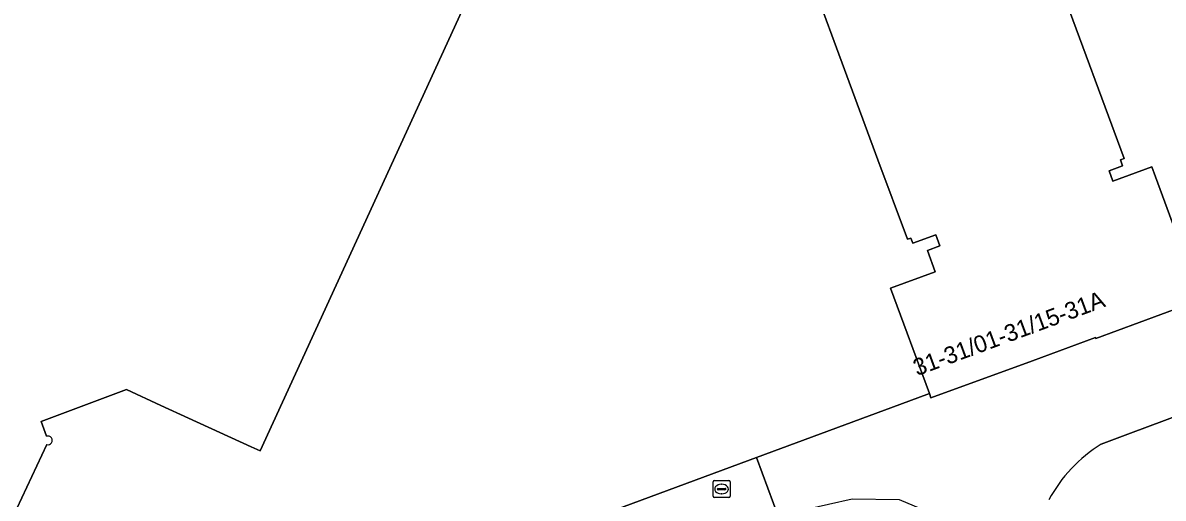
# Model space of a CAD drawing. Extents: x 160806 to 161707, y 383696 to 384148.
# Drawn here: x 160990.2 to 161057.4, y 383902 to 383930 of the extents above; entities that cross this region are included whole.
import ezdxf

# ---------------------------------------------------------------- set-up
doc = ezdxf.new("R2010")
doc.units = 0
for name, color, linetype in [('IMGEO_Pand', 7, 'Continuous'), ('IMGEO_Pand_nummerreeks', 7, 'Continuous'), ('IMGEO_Rijbaan_lokaal_gesloten', 7, 'Continuous'), ('IMGEO_Rijbaan_lokaal_open', 7, 'Continuous'), ('IMGEO_Rioolput', 7, 'Continuous'), ('IMGEO_Terreindeel_gesloten', 7, 'Continuous'), ('IMGEO_Voetpad_open', 7, 'Continuous')]:
    doc.layers.add(name, color=color, linetype=linetype)

msp = doc.modelspace()

# ---------------------------------------------------------------- linework, layer by layer
at = {"layer": 'IMGEO_Pand'}
for points in [[(161058.676, 383916.245), (161056.943, 383920.935), (161056.726, 383921.521), (161054.435, 383920.674), (161054.205, 383921.295), (161055.004, 383921.59), (161054.873, 383921.943), (161055.094, 383922.025), (161047.599, 383942.307)], [(161034.831, 383937.553), (161040.599, 383921.947), (161042.332, 383917.257), (161042.54, 383917.334), (161042.655, 383917.023), (161043.998, 383917.519), (161044.238, 383916.87), (161043.507, 383916.6), (161043.975, 383915.334), (161041.34, 383914.377), (161043.624, 383908.173), (161043.72, 383907.911), (161049.695, 383910.101), (161053.4, 383911.47), (161053.421, 383911.413), (161058.534, 383913.302)], [(160991.646, 383905.654), (160991.322, 383906.532), (160996.345, 383908.4), (160998.375, 383907.467), (161000, 383906.721), (161003.7, 383905.021), (161004.216, 383904.789), (161006.3, 383909.334), (161016.1, 383930.706)], [(160989.606, 383900.762), (160991.657, 383905.16)]]:
    msp.add_lwpolyline(points, dxfattribs=at)
msp.add_arc((160991.722, 383905.409), 0.257, 255.32376, 107.22745, dxfattribs=at)
at = {"layer": 'IMGEO_Rijbaan_lokaal_gesloten'}
for points in [[(161060.631, 383907.756), (161066.551, 383909.97), (161065.506, 383912.776), (161064.49, 383915.503), (161058.534, 383913.302), (161053.421, 383911.413), (161053.4, 383911.47), (161049.695, 383910.101), (161043.72, 383907.911), (161043.624, 383908.173), (161042.42, 383907.727), (161033.437, 383904.394), (161034.783, 383900.781), (161036.286, 383901.335), (161039.086, 383901.965), (161041.846, 383901.934), (161043.103, 383901.391), (161044.432, 383899.991), (161044.961, 383898.608), (161045.706, 383896.613), (161049.823, 383898.173)], [(161053.746, 383905.182), (161055.478, 383905.83), (161060.631, 383907.756)]]:
    msp.add_lwpolyline(points, dxfattribs=at)
msp.add_arc((161058.187, 383897.914), 8.517, 121.42514, 152.03536, dxfattribs=at)
at = {"layer": 'IMGEO_Rijbaan_lokaal_open'}
msp.add_lwpolyline([(160943.158, 383950.097), (160950.161, 383931.007), (160960.137, 383903.811), (160959.806, 383902.516), (160968.05, 383879.828), (160984.869, 383885.974), (160986.341, 383885.715), (160990.275, 383885.032), (160991.432, 383884.817), (161000, 383887.972), (161034.783, 383900.781), (161033.437, 383904.394), (161000, 383892.005), (160990.074, 383888.326), (160982.677, 383889.672), (160974.531, 383886.634), (160974.125, 383886.483), (160971.037, 383887.859), (160947.548, 383951.917), (160947.428, 383954.476), (160941.963, 383951.859)], close=True, dxfattribs=at)
at = {"layer": 'IMGEO_Rioolput'}
for p, q in [((161030.889, 383902.116), (161030.889, 383902.968)), ((161030.964, 383903.042), (161031.816, 383903.042)), ((161031.89, 383902.968), (161031.89, 383902.116)), ((161031.148, 383902.536), (161031.148, 383902.548)), ((161031.586, 383902.499), (161031.188, 383902.499)), ((161031.191, 383902.585), (161031.589, 383902.585)), ((161031.4, 383902.262), (161031.375, 383902.262)), ((161031.377, 383902.822), (161031.402, 383902.822)), ((161031.632, 383902.548), (161031.632, 383902.536)), ((161031.816, 383902.042), (161030.964, 383902.042))]:
    msp.add_line(p, q, dxfattribs=at)
for points in [[(161030.889, 383902.116), (161030.889, 383902.968)], [(161030.964, 383903.042), (161031.816, 383903.042)], [(161031.89, 383902.968), (161031.89, 383902.116)], [(161031.816, 383902.042), (161030.964, 383902.042)]]:
    msp.add_lwpolyline(points, dxfattribs=at)
for centre, radius, start, end in [((161030.966, 383902.966), 0.0765, 91.55205, 178.44795), ((161030.966, 383902.966), 0.0765, 91.55205, 178.44795), ((161031.814, 383902.966), 0.0765, 1.55205, 88.44795), ((161031.814, 383902.966), 0.0765, 1.55205, 88.44795), ((161031.188, 383902.545), 0.0403, 85.87752, 175.75265), ((161031.185, 383902.535), 0.0366, 178.93798, 274.71019), ((161031.589, 383902.542), 0.043, 264.86636, 352.45326), ((161031.593, 383902.547), 0.0386, 1.73085, 96.63898), ((161030.966, 383902.118), 0.0765, 181.55205, 268.44795), ((161030.966, 383902.118), 0.0765, 181.55205, 268.44795), ((161031.814, 383902.118), 0.0765, 271.55205, 358.44795), ((161031.814, 383902.118), 0.0765, 271.55205, 358.44795)]:
    msp.add_arc(centre, radius, start, end, dxfattribs=at)
for centre, major_axis, ratio, start_param, end_param in [((161031.376, 383902.542), (-0.387, 0.002), 0.722429, 4.712389, 7.853982), ((161031.401, 383902.542), (-0.39, 0.002), 0.717154, 1.570796, 4.712389)]:
    msp.add_ellipse(centre, major_axis=major_axis, ratio=ratio, start_param=start_param, end_param=end_param, dxfattribs=at)
at = {"layer": 'IMGEO_Terreindeel_gesloten'}
for points in [[(161047.599, 383942.307), (161055.094, 383922.025), (161054.873, 383921.943), (161055.004, 383921.59), (161054.205, 383921.295), (161054.435, 383920.674), (161056.726, 383921.521), (161056.943, 383920.935), (161058.676, 383916.245)], [(160990.074, 383888.326), (161000, 383892.005), (161033.437, 383904.394), (161042.42, 383907.727), (161043.624, 383908.173), (161041.34, 383914.377), (161043.975, 383915.334), (161043.507, 383916.6), (161044.238, 383916.87), (161043.998, 383917.519), (161042.655, 383917.023), (161042.54, 383917.334), (161042.332, 383917.257), (161040.599, 383921.947), (161034.831, 383937.553)], [(161016.1, 383930.706), (161006.3, 383909.334), (161004.216, 383904.789), (161003.7, 383905.021), (161000, 383906.721), (160998.375, 383907.467), (160996.345, 383908.4), (160991.322, 383906.532), (160991.646, 383905.654)], [(160991.657, 383905.16), (160989.606, 383900.762)]]:
    msp.add_lwpolyline(points, dxfattribs=at)
msp.add_arc((160991.722, 383905.409), 0.257, 255.32376, 107.22745, dxfattribs=at)
at = {"layer": 'IMGEO_Voetpad_open'}
msp.add_lwpolyline([(161050.88, 383898.651), (161055.575, 383900.371), (161057.923, 383901.231), (161062.646, 383902.961), (161060.631, 383907.756), (161055.478, 383905.83), (161053.746, 383905.182)], dxfattribs=at)
msp.add_arc((161058.187, 383897.914), 8.517, 121.42514, 152.03536, dxfattribs=at)

# ---------------------------------------------------------------- texts
at = {"layer": 'IMGEO_Pand_nummerreeks'}
msp.add_text('31-31/01-31/15-31A', height=1, rotation=20.27698, dxfattribs=at).set_placement((161042.899, 383909.19))

doc.saveas('drawing.dxf')
